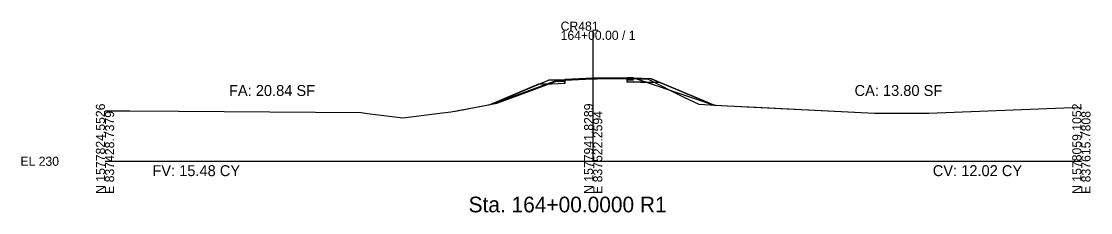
# Model space of a CAD drawing. Extents: x -26 to 303, y -16 to 6048.
# Drawn here: x -25.7 to 302.8, y 984.3 to 1042.8 of the extents above; entities that cross this region are included whole.
import ezdxf

# ---------------------------------------------------------------- set-up
doc = ezdxf.new("R2010")
doc.units = 0
for name, color, linetype in [('ASPHALT_19MM1', 7, 'Continuous'), ('ASPHALT_9_5MM1', 7, 'Continuous'), ('Draft_XS_Grid', 7, 'Continuous'), ('Draft_XS_Text', 7, 'Continuous'), ('DTM_P_FINISHED_GRADE2', 7, 'Continuous'), ('DTM_TEMP_DROP', 7, 'Continuous'), ('DTM_X_GROUND', 7, 'Continuous'), ('TRANS_PAVED_SHOULDERS', 7, 'Continuous'), ('XS_CELL', 7, 'Continuous'), ('XS_M_SHAPES_EARTHWORK', 7, 'Continuous'), ('XS_P_ASPHALT', 7, 'Continuous'), ('XS_P_GROUND', 7, 'Continuous'), ('XS_P_NULL_POINT', 7, 'Continuous'), ('XS_P_SHOULDER', 7, 'Continuous'), ('XS_P_SUBGRADE_GRANULAR', 7, 'Continuous'), ('XS_P_SUBGRADE_LEVELING', 7, 'Continuous'), ('XS_P_SUBGRADE_MILLING', 7, 'Continuous'), ('XS_SHEET_EW_TX_AREA', 7, 'Continuous'), ('XS_SHEET_EW_TX_VOLUME', 7, 'Continuous')]:
    doc.layers.add(name, color=color, linetype=linetype)

msp = doc.modelspace()

# ---------------------------------------------------------------- linework, layer by layer
at = {"layer": 'ASPHALT_19MM1'}
for points in [[(160.39, 1025.22), (160.39, 1024.95), (162.39, 1024.97), (162.39, 1025.24), (160.39, 1025.22)], [(141.24, 1024.73), (141.24, 1024.46), (139.24, 1024.37), (139.24, 1024.64), (141.24, 1024.73)]]:
    msp.add_lwpolyline(points, dxfattribs=at)
at = {"layer": 'ASPHALT_9_5MM1'}
for points in [[(141.24, 1025.06), (141.24, 1024.94), (139.24, 1024.85), (139.24, 1024.98), (141.24, 1025.06)], [(160.39, 1025.55), (160.39, 1025.43), (162.39, 1025.45), (162.39, 1025.57), (160.39, 1025.55)]]:
    msp.add_lwpolyline(points, dxfattribs=at)
at = {"layer": 'DTM_P_FINISHED_GRADE2'}
msp.add_lwpolyline([(118.47, 1017.44), (118.47, 1017.44), (123.8, 1019.62), (136.24, 1024.84), (139.24, 1024.98), (141.24, 1025.06), (150, 1025.45), (160.39, 1025.55), (162.39, 1025.57), (167.58, 1025.36), (187.17, 1017.2)], dxfattribs=at)
at = {"layer": 'DTM_X_GROUND'}
for points in [[(0, 1015.43), (2.46, 1015.43), (3.07, 1015.42), (3.28, 1015.42), (3.87, 1015.43), (4.48, 1015.43), (5.12, 1015.44), (5.78, 1015.45), (6.47, 1015.45), (6.85, 1015.46), (7.58, 1015.45), (22.58, 1015.34), (78.7, 1014.92), (80.62, 1014.67), (91.54, 1013.29), (102.93, 1014.74), (106.23, 1015.12), (107.52, 1015.37), (108.17, 1015.49), (108.48, 1015.55), (118.47, 1017.44), (118.47, 1017.44), (124.15, 1019.46), (124.71, 1019.66), (139.24, 1024.98), (139.24, 1024.98), (141.24, 1025.06), (141.24, 1025.06), (150, 1025.45), (150, 1025.45), (160.39, 1025.55), (160.39, 1025.55), (162.39, 1025.57), (187.17, 1017.2), (187.17, 1017.2), (191.23, 1016.99), (199.93, 1016.54), (236.39, 1014.76), (253.09, 1014.74), (294.64, 1016.32), (300, 1016.46)], [(0, 1015.43), (2.46, 1015.43), (3.07, 1015.42), (3.28, 1015.42), (3.87, 1015.43), (4.48, 1015.43), (5.12, 1015.44), (5.78, 1015.45), (6.47, 1015.45), (6.85, 1015.46), (7.58, 1015.45), (22.58, 1015.34), (78.7, 1014.92), (80.62, 1014.67), (91.54, 1013.29), (102.93, 1014.74), (106.23, 1015.12), (108.17, 1015.49), (120.42, 1017.81), (124.03, 1019.15), (139.24, 1024.73), (149.68, 1025.26), (150.39, 1025.29), (151.23, 1025.29), (162.39, 1025.34), (164.27, 1025.24), (166.87, 1025.12), (177.87, 1019.66), (182.45, 1017.47), (191.23, 1016.97), (236.39, 1014.76), (253.09, 1014.74), (294.64, 1016.32), (300, 1016.46)]]:
    msp.add_lwpolyline(points, dxfattribs=at)
at = {"layer": 'TRANS_PAVED_SHOULDERS'}
for points in [[(160.39, 1025.43), (160.39, 1025.22), (162.39, 1025.24), (162.39, 1025.45), (160.39, 1025.43)], [(141.24, 1024.94), (141.24, 1024.73), (139.24, 1024.64), (139.24, 1024.85), (141.24, 1024.94)]]:
    msp.add_lwpolyline(points, dxfattribs=at)
at = {"layer": 'XS_CELL'}
for p, q in [((150, 1000), (150, 1040)), ((0, 1000), (150, 1000)), ((150, 1000), (300, 1000))]:
    msp.add_line(p, q, dxfattribs=at)
at = {"layer": 'XS_M_SHAPES_EARTHWORK'}
for points in [[(135.57, 1023.63), (139.24, 1024.98), (141.24, 1025.06), (150, 1025.45), (160.39, 1025.55), (162.39, 1025.57), (166.39, 1024.22), (164.39, 1024.26), (162.39, 1024.3), (160.39, 1024.28), (160.39, 1024.95), (160.39, 1025.22), (160.39, 1025.33), (151.23, 1025.29), (150.39, 1025.29), (150, 1025.27), (149.68, 1025.26), (141.24, 1024.83), (141.24, 1024.83), (141.24, 1024.73), (141.24, 1024.46), (141.24, 1023.79), (139.24, 1023.7), (137.24, 1023.66)], [(118.47, 1017.44), (124.15, 1019.46), (124.71, 1019.66), (135.57, 1023.63), (133.22, 1023.58)], [(166.39, 1024.22), (187.17, 1017.2), (170.52, 1024.14)]]:
    msp.add_lwpolyline(points, close=True, dxfattribs=at)
at = {"layer": 'XS_P_ASPHALT'}
msp.add_lwpolyline([(141.24, 1025.06), (141.24, 1024.94), (141.24, 1024.94), (150, 1025.33), (150, 1025.33), (160.39, 1025.43), (160.39, 1025.55), (160.39, 1025.55), (150, 1025.45), (150, 1025.45), (141.24, 1025.06), (141.24, 1025.06), (141.24, 1025.06)], dxfattribs=at)
at = {"layer": 'XS_P_GROUND'}
for points in [[(187.17, 1017.2), (187.17, 1017.2), (167.58, 1025.36)], [(118.47, 1017.44), (118.47, 1017.44), (136.24, 1024.84)]]:
    msp.add_lwpolyline(points, dxfattribs=at)
at = {"layer": 'XS_P_SHOULDER'}
for points in [[(162.39, 1025.57), (167.58, 1025.36)], [(139.24, 1024.98), (136.24, 1024.84)]]:
    msp.add_lwpolyline(points, dxfattribs=at)
at = {"layer": 'XS_P_SUBGRADE_GRANULAR'}
for points in [[(141.24, 1023.79), (141.24, 1025.06)], [(160.39, 1024.28), (160.39, 1025.55)], [(139.24, 1023.7), (137.24, 1023.66), (133.22, 1023.58)], [(141.24, 1023.79), (139.24, 1023.7)], [(160.39, 1024.28), (162.39, 1024.3)], [(162.39, 1024.3), (164.39, 1024.26), (170.52, 1024.14)]]:
    msp.add_lwpolyline(points, dxfattribs=at)
at = {"layer": 'XS_P_SUBGRADE_LEVELING'}
msp.add_lwpolyline([(160.39, 1025.43), (160.39, 1025.43), (160.39, 1025.43), (160.39, 1025.33), (160.39, 1025.33), (151.23, 1025.29), (151.23, 1025.29), (150.39, 1025.29), (150, 1025.27), (150, 1025.27), (149.68, 1025.26), (149.68, 1025.26), (141.24, 1024.83), (141.24, 1024.83), (141.24, 1024.94), (141.24, 1024.94), (141.24, 1024.94), (149.68, 1025.31), (149.68, 1025.31), (150, 1025.33), (150, 1025.33), (150.39, 1025.33), (151.23, 1025.34), (151.23, 1025.34), (160.39, 1025.43)], dxfattribs=at)
at = {"layer": 'XS_P_SUBGRADE_MILLING'}
msp.add_lwpolyline([(141.24, 1024.83), (141.24, 1024.83), (149.68, 1025.26), (149.68, 1025.26), (150, 1025.27), (150, 1025.27), (150.39, 1025.29), (151.23, 1025.29), (151.23, 1025.29), (160.39, 1025.33), (160.39, 1025.33)], dxfattribs=at)
msp.add_lwpolyline([(141.24, 1024.83), (141.24, 1024.83), (149.68, 1025.26), (149.68, 1025.26), (150, 1025.27), (150, 1025.27), (150.39, 1025.29), (151.23, 1025.29), (151.23, 1025.29), (160.39, 1025.33), (160.39, 1025.33)], dxfattribs=at)

# ---------------------------------------------------------------- texts
at = {"layer": 'Draft_XS_Grid'}
msp.add_text('-', height=0.0001, dxfattribs=at).set_placement((0, 1000))
at = {"layer": 'Draft_XS_Text'}
msp.add_text('Sta. 164+00.0000 R1', height=4.8, dxfattribs=at).set_placement((111.72, 984.35))
at = {"layer": 'DTM_TEMP_DROP'}
for p in [(118.4, 1017.32), (187.09, 1017.08)]:
    msp.add_text('X', height=0.24, dxfattribs=at).set_placement(p)
at = {"layer": 'XS_CELL'}
for s, p in [('CR481', (140, 1040)), ('164+00.00 / 1', (140, 1037.2)), ('EL 230', (-26, 998.6))]:
    msp.add_text(s, height=2.8, dxfattribs=at).set_placement(p)
for s, p in [('N 1577824.5526', (0, 990)), ('E 837428.7379', (2.8, 990)), ('N 1577941.8289', (150, 990)), ('E 837522.2594', (152.8, 990)), ('N 1578059.1052', (300, 990)), ('E 837615.7808', (302.8, 990))]:
    msp.add_text(s, height=2.8, rotation=90, dxfattribs=at).set_placement(p)
at = {"layer": 'XS_P_GROUND'}
for p in [(167.5, 1025.24), (136.16, 1024.72)]:
    msp.add_text('X', height=0.24, dxfattribs=at).set_placement(p)
at = {"layer": 'XS_P_NULL_POINT'}
for p in [(139.16, 1024.86), (141.16, 1024.94), (149.92, 1025.33), (160.31, 1025.43), (162.31, 1025.45)]:
    msp.add_text('X', height=0.24, dxfattribs=at).set_placement(p)
at = {"layer": 'XS_P_SUBGRADE_GRANULAR'}
for p in [(118.4, 1017.32), (187.09, 1017.08)]:
    msp.add_text('X', height=0.24, dxfattribs=at).set_placement(p)
at = {"layer": 'XS_SHEET_EW_TX_AREA'}
for s, p in [('FA: 20.84 SF', (38.09, 1020)), ('CA: 13.80 SF', (230.3, 1020))]:
    msp.add_text(s, height=3.36, dxfattribs=at).set_placement(p)
at = {"layer": 'XS_SHEET_EW_TX_VOLUME'}
for s, p in [('FV: 15.48 CY', (14.55, 995.44)), ('CV: 12.02 CY', (254.34, 995.44))]:
    msp.add_text(s, height=3.36, dxfattribs=at).set_placement(p)

doc.saveas('drawing.dxf')
